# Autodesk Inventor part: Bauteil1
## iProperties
Created: 2005-05
Part Number: Bauteil1
Document SubType Name: Modeling
Designer: Target
Manufacturer: Standard
Standards Organization: Custom
Cost Center: 0,013 kg
Authority: 12997 mm^3
SaveDate: 2005-05-30
SaveTime: 15:10
TotalMass: 0,013 kg
TotalVolume: 12997 mm^3
Author: Target
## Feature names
1. Extrusion2
2. Trennen1
3. Extrusion3
